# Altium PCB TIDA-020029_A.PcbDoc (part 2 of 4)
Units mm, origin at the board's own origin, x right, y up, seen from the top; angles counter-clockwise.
Board outline 267.5 x 53.5 mm, 2 copper layers (Top Layer, Bottom Layer), stack 1.575 mm thick; 255 components, 134 nets, 990 pads, 1977 vias.
Unrouted connection lines stored in the file: 9.
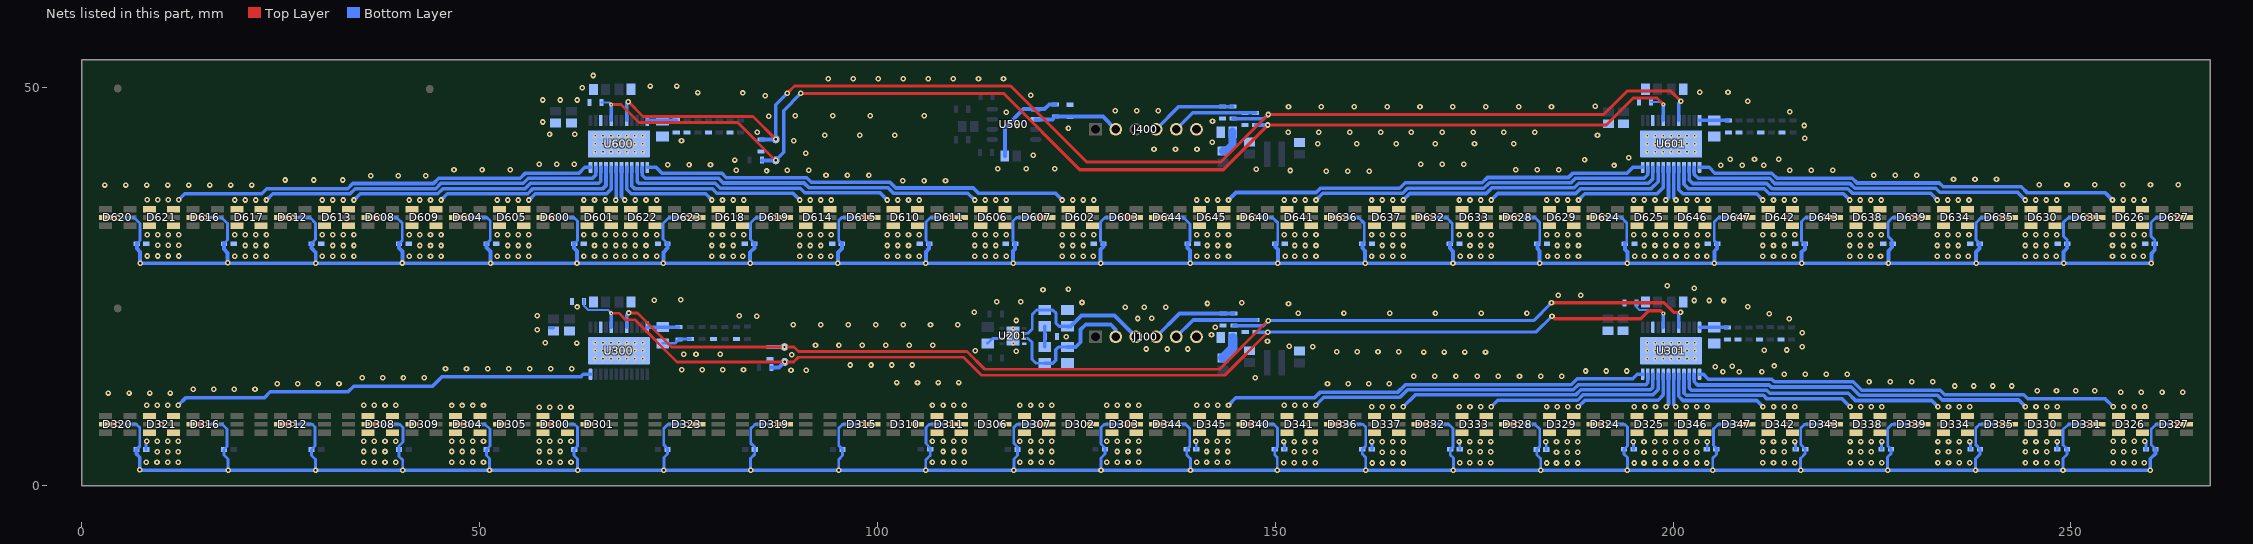
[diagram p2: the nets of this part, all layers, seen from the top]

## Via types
v1: diameter 0.7, hole 0.3, Top Layer to Bottom Layer, tented both sides, 1881 vias
v2: diameter 0.5, hole 0.2, Top Layer to Bottom Layer, tented both sides, 96 vias

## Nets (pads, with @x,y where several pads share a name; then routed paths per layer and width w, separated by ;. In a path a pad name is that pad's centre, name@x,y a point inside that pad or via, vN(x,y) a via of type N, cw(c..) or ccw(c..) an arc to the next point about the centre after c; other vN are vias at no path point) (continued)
1OUT11: C302.2 D321.1 D321.3 D321.4 D321.6 U300.24 | length 54.5
  Bottom Layer w0.254: v1@8.059,5.507 v1(8.128,5.577)
  Bottom Layer w0.35: C302.2@8.059,4.535 v1@8.059,5.507
  Bottom Layer w0.45: v1(12.123,10.098) 13.088,11.063 22.962,11.063 23.688,11.789 33.452,11.789 34.163,12.501 44.059,12.501 45.212,13.654 62.662,13.654 63.008,14 U300.24@63.925,14
  other v1: 8.103,2.908 9.432,2.908 10.761,2.908 12.09,2.908 9.464,4.256 10.794,4.256 12.123,4.256 9.457,5.577 10.787,5.577 12.116,5.577 10,7.7 8.135,10.098 9.464,10.098 10.794,10.098
2OUT0: C332.2 D326.1 D326.3 D326.4 D326.6 U301.13 | length 54.7
  Bottom Layer w0.35: v1(259.309,5.559) 259.445,5.423 C332.2@259.445,4.561
  Bottom Layer w0.45: U301.13@203.325,14 203.827,14 204.445,13.383 212.423,13.383 212.763,13.042 222.661,13.042 ; 222.733,12.976 223.719,11.99 233.576,11.99 234.163,11.404 244.092,11.404 244.577,10.919 254.3,10.919 v1(255.321,9.898)
  other v1: 255.321,2.891 256.65,2.891 257.979,2.891 259.209,2.891 255.321,4.264 256.65,4.264 257.979,4.264 255.321,5.559 256.65,5.559 257.979,5.559 256.65,9.898 257.979,9.898 259.309,9.898
2OUT1: C331.2 D330.1 D330.3 D330.4 D330.6 U301.14 | length 44.9
  Bottom Layer w0.254: C331.2@248.285,4.588 C331.2@248.312,4.561
  Bottom Layer w0.35: C331.2@248.285,4.588 v1(248.285,5.534)
  Bottom Layer w0.45: U301.14@202.675,14 202.675,13.05 203.085,12.64 212.109,12.64 212.357,12.392 222.392,12.392 223.444,11.34 233.233,11.34 233.82,10.754 243.441,10.754 v1(244.297,9.898)
  other v1: 244.297,2.865 245.626,2.865 246.956,2.865 248.285,2.865 244.297,4.239 245.626,4.239 246.956,4.239 244.297,5.534 245.626,5.534 246.956,5.534 245.626,9.898 246.956,9.898 248.285,9.898
2OUT2: C330.2 D334.1 D334.3 D334.4 D334.6 U301.15 | length 35
  Bottom Layer w0.35: v1(237.287,5.534) 237.388,5.432 C330.2@237.388,4.561
  Bottom Layer w0.45: U301.15@202.025,14 202.025,12.276 202.311,11.99 211.753,11.99 212.139,11.605 222.021,11.605 222.936,10.69 232.507,10.69 v1(233.299,9.898)
  other v1: 233.299,2.865 234.628,2.865 235.958,2.865 237.287,2.865 233.299,4.239 234.628,4.239 235.958,4.239 233.299,5.534 234.628,5.534 235.958,5.534 234.628,9.898 235.958,9.898 237.287,9.898
2OUT3: C329.2 D338.1 D338.3 D338.4 D338.6 U301.16 | length 25
  Bottom Layer w0.254: v1@226.204,5.5 v1(226.238,5.534)
  Bottom Layer w0.35: C329.2@226.204,4.561 v1@226.204,5.5
  Bottom Layer w0.45: U301.16@201.375,14 201.375,11.616 201.651,11.34 211.364,11.34 211.811,10.893 221.255,10.893 v1(222.25,9.898)
  other v1: 222.25,2.865 223.579,2.865 224.909,2.865 226.238,2.865 222.25,4.239 223.579,4.239 224.909,4.239 222.25,5.534 223.579,5.534 224.909,5.534 223.579,9.898 224.909,9.898 226.238,9.898
2OUT4: C328.2 D342.1 D342.3 D342.4 D342.6 U301.17 | length 14.9
  Bottom Layer w0.35: v1(215.288,5.534) 215.406,5.416 C328.2@215.406,4.561
  Bottom Layer w0.45: U301.17@200.725,14 200.725,11.209 201.244,10.69 210.51,10.69 v1(211.303,9.898)
  other v1: 211.3,2.865 212.629,2.865 213.958,2.865 215.288,2.865 211.3,4.239 212.629,4.239 213.958,4.239 211.3,5.534 212.629,5.534 213.958,5.534 212.632,9.898 213.961,9.898 215.29,9.898
2OUT5: C327.2 D346.1 D346.3 D346.4 D346.6 U301.18 | length 5.2
  Bottom Layer w0.254: C327.2@204.25,4.561 C327.2@204.313,4.624
  Bottom Layer w0.35: C327.2@204.313,4.624 v1(204.313,5.509)
  Bottom Layer w0.45: U301.18@200.075,14 200.075,10.153 v1@200.325,9.903
  other v1: 200.325,2.84 201.654,2.84 202.984,2.84 204.213,2.84 200.325,4.213 201.654,4.213 202.984,4.213 200.325,5.509 201.654,5.509 202.984,5.509 200.325,9.898 201.654,9.898 202.984,9.898 204.313,9.898
2OUT6: C326.2 D325.1 D325.3 D325.4 D325.6 U301.19 | length 5.2
  Bottom Layer w0.254: v1(195.021,5.509) v1@195.039,5.491
  Bottom Layer w0.35: C326.2@195.039,4.561 v1@195.039,5.491
  Bottom Layer w0.45: v1@199.111,9.903 199.425,10.217 U301.19@199.425,14
  other v1: 195.121,2.842 196.35,2.842 197.68,2.842 199.009,2.842 196.35,4.213 197.68,4.213 199.009,4.213 196.35,5.509 197.68,5.509 199.009,5.509 195.139,9.898 196.468,9.898 197.797,9.898 199.126,9.898
2OUT7: C325.2 D329.1 D329.3 D329.4 D329.6 U301.20 | length 14.9
  Bottom Layer w0.254: v1(184.023,5.509) v1@184.059,5.473
  Bottom Layer w0.35: C325.2@184.059,4.535 v1@184.059,5.473
  Bottom Layer w0.45: v1@188.087,9.903 188.925,10.741 198.12,10.741 198.775,11.396 U301.20@198.775,14
  other v1: 184.123,2.842 185.352,2.842 186.682,2.842 188.011,2.842 185.352,4.213 186.682,4.213 188.011,4.213 185.352,5.509 186.682,5.509 188.011,5.509 184.099,9.898 185.428,9.898 186.758,9.898 188.087,9.898
2OUT8: C324.2 D333.1 D333.3 D333.4 D333.6 U301.21 | length 24.8
  Bottom Layer w0.35: v1(173.101,5.534) 173.193,5.442 C324.2@173.193,4.561
  Bottom Layer w0.45: v1(177.14,9.898) 177.983,10.741 188.006,10.741 188.656,11.391 197.429,11.391 198.125,12.087 U301.21@198.125,14
  other v1: 173.201,2.867 174.43,2.867 175.76,2.867 177.089,2.867 174.43,4.239 175.76,4.239 177.089,4.239 174.43,5.534 175.76,5.534 177.089,5.534 173.152,9.898 174.481,9.898 175.81,9.898
2OUT9: C321.2 D337.1 D337.3 D337.4 D337.6 U301.22 | length 35
  Bottom Layer w0.35: v1(162.103,5.509) 162.144,5.467 C321.2@162.144,4.561
  Bottom Layer w0.45: v1(166.091,9.898) 167.584,11.391 187.737,11.391 188.387,12.041 197.159,12.041 197.475,12.357 U301.22@197.475,14
  other v1: 162.203,2.842 163.432,2.842 164.761,2.842 166.091,2.842 163.432,4.213 164.761,4.213 166.091,4.213 163.432,5.509 164.761,5.509 166.091,5.509 162.103,9.898 163.432,9.898 164.761,9.898
2OUT10: C320.2 D341.1 D341.3 D341.4 D341.6 U301.23 | length 45
  Bottom Layer w0.35: v1(151.054,5.534) 151.146,5.442 C320.2@151.146,4.569
  Bottom Layer w0.45: v1(155.092,10.098) 156.078,11.084 165.671,11.084 166.629,12.041 187.467,12.041 188.117,12.691 196.59,12.691 196.825,12.926 U301.23@196.825,14
  other v1: 151.054,2.867 152.383,2.867 153.712,2.867 155.042,2.867 152.383,4.239 153.712,4.239 155.042,4.239 152.383,5.534 153.712,5.534 155.042,5.534 151.105,10.098 152.434,10.098 153.763,10.098
2OUT11: C319.2 D345.1 D345.3 D345.4 D345.6 U301.24 | length 54.7
  Bottom Layer w0.254: v1(140.03,5.577) v1@140.071,5.536
  Bottom Layer w0.35: C319.2@140.071,4.561 v1@140.071,5.536
  Bottom Layer w0.45: v1(144.12,10.098) 145.042,11.02 154.94,11.02 155.676,11.756 165.424,11.756 166.359,12.691 187.198,12.691 187.941,13.433 194.945,13.433 195.512,14 U301.24@196.175,14
  other v1: 140.13,2.91 141.359,2.91 142.689,2.91 144.018,2.91 141.359,4.281 142.689,4.281 144.018,4.281 141.359,5.577 142.689,5.577 144.018,5.577 140.132,10.098 141.461,10.098 142.79,10.098
3OUT0: C615.2 D602.1 D602.3 D602.4 D602.6 U600.13 | length 53.8
  Bottom Layer w0.45: U600.13@71.075,40 72.157,40 72.873,39.284 80.401,39.284 81.001,38.685 91.095,38.685 91.669,38.111 101.575,38.111 102.276,37.41 112.024,37.41 112.7,36.735 122.37,36.735 v1(123.208,35.897)
  other v1: 123.208,28.834 124.538,28.834 125.867,28.834 127.096,28.834 123.208,30.182 124.538,30.182 125.867,30.182 123.208,31.528 124.538,31.528 125.867,31.528 127.196,31.528 124.538,35.897 125.867,35.897 127.196,35.897
3OUT1: C614.2 D606.1 D606.3 D606.4 D606.6 U600.14 | length 44.1
  Bottom Layer w0.45: U600.14@70.425,40 70.425,39.005 70.796,38.634 80.02,38.634 80.62,38.035 90.765,38.035 91.338,37.461 101.306,37.461 102.006,36.76 111.347,36.76 v1(112.21,35.897)
  other v1: 112.21,28.834 113.539,28.834 114.869,28.834 116.198,28.834 112.21,30.182 113.539,30.182 114.869,30.182 112.21,31.528 113.539,31.528 114.869,31.528 116.198,31.528 113.539,35.897 114.869,35.897 116.198,35.897
3OUT2: C613.2 D610.1 D610.3 D610.4 D610.6 U600.15 | length 34.2
  Bottom Layer w0.45: U600.15@69.775,40 69.775,38.232 70.023,37.984 79.614,37.984 80.213,37.385 90.282,37.385 90.856,36.811 100.323,36.811 v1(101.237,35.897)
  other v1: 101.237,28.834 102.567,28.834 103.896,28.834 105.225,28.834 101.237,30.182 102.567,30.182 103.896,30.182 101.237,31.528 102.567,31.528 103.896,31.528 105.225,31.528 102.567,35.897 103.896,35.897 105.225,35.897
3OUT3: C612.2 D614.1 D614.3 D614.4 D614.6 U600.16 | length 24.2
  Bottom Layer w0.45: U600.16@69.125,40 69.125,37.653 69.444,37.334 79.208,37.334 79.807,36.735 89.376,36.735 v1(90.214,35.897)
  other v1: 90.214,28.834 91.543,28.834 92.872,28.834 94.102,28.834 90.214,30.182 91.543,30.182 92.872,30.182 90.214,31.528 91.543,31.528 92.872,31.528 94.202,31.528 91.543,35.897 92.872,35.897 94.202,35.897
3OUT4: C611.2 D618.1 D618.3 D618.4 D618.6 U600.17 | length 14
  Bottom Layer w0.45: U600.17@68.475,40 68.475,37.26 69.051,36.684 78.403,36.684 v1(79.19,35.897)
  other v1: 79.19,28.834 80.519,28.834 81.849,28.834 83.078,28.834 79.19,30.182 80.519,30.182 81.849,30.182 79.19,31.528 80.519,31.528 81.849,31.528 83.178,31.528 80.519,35.897 81.849,35.897 83.178,35.897
3OUT5: C610.2 D622.1 D622.3 D622.4 D622.6 U600.18 | length 4.3
  Bottom Layer w0.45: U600.18@67.825,40 67.825,36.315 v1(68.243,35.897)
  other v1: 68.243,28.834 69.572,28.834 70.901,28.834 72.231,28.834 68.243,30.182 69.572,30.182 70.901,30.182 68.243,31.528 69.572,31.528 70.901,31.528 72.231,31.528 69.572,35.897 70.901,35.897 72.231,35.897
3OUT6: C609.2 D601.1 D601.3 D601.4 D601.6 U600.19 | length 4.1
  Bottom Layer w0.45: v1(67.088,35.897) 67.175,35.984 U600.19@67.175,40
  other v1: 63.1,28.834 64.429,28.834 65.759,28.834 67.088,28.834 64.429,30.182 65.759,30.182 67.088,30.182 63.1,31.528 64.429,31.528 65.759,31.528 67.088,31.528 63.1,35.897 64.429,35.897 65.759,35.897
3OUT7: C608.2 D605.1 D605.3 D605.4 D605.6 U600.20 | length 13.6
  Bottom Layer w0.45: v1(56.185,35.897) 56.972,36.684 65.938,36.684 66.525,37.271 U600.20@66.525,40
  other v1: 52.197,28.834 53.526,28.834 54.856,28.834 56.185,28.834 53.526,30.182 54.856,30.182 56.185,30.182 52.197,31.528 53.526,31.528 54.856,31.528 56.185,31.528 52.197,35.897 53.526,35.897 54.856,35.897
3OUT8: C607.2 D609.1 D609.3 D609.4 D609.6 U600.21 | length 23.8
  Bottom Layer w0.45: v1(45.138,35.897) 45.925,36.684 56.053,36.684 56.703,37.334 65.498,37.334 65.875,37.711 U600.21@65.875,40
  other v1: 41.15,28.834 42.479,28.834 43.809,28.834 45.138,28.834 42.479,30.182 43.809,30.182 45.138,30.182 41.15,31.528 42.479,31.528 43.809,31.528 45.138,31.528 41.15,35.897 42.479,35.897 43.809,35.897
3OUT9: C604.2 D613.1 D613.3 D613.4 D613.6 U600.22 | length 33.8
  Bottom Layer w0.45: v1(34.188,35.897) 34.963,36.672 44.742,36.672 45.405,37.334 55.728,37.334 56.378,37.984 64.957,37.984 65.225,38.252 U600.22@65.225,40
  other v1: 30.201,28.834 31.53,28.834 32.859,28.834 34.188,28.834 31.53,30.182 32.859,30.182 34.188,30.182 30.201,31.528 31.53,31.528 32.859,31.528 34.188,31.528 30.201,35.897 31.53,35.897 32.859,35.897
3OUT10: C603.2 D617.1 D617.3 D617.4 D617.6 U600.23 | length 43.7
  Bottom Layer w0.45: v1(23.19,35.897) 23.965,36.672 33.693,36.672 34.343,37.322 44.473,37.322 45.136,37.984 55.458,37.984 56.108,38.634 64.18,38.634 64.575,39.029 U600.23@64.575,40
  other v1: 19.202,28.834 20.532,28.834 21.861,28.834 23.19,28.834 20.532,30.182 21.861,30.182 23.19,30.182 19.202,31.528 20.532,31.528 21.861,31.528 23.19,31.528 19.202,35.897 20.532,35.897 21.861,35.897
3OUT11: C602.2 D621.1 D621.3 D621.4 D621.6 U600.24 | length 53.4
  Bottom Layer w0.45: v1(12.174,35.922) 12.936,36.684 22.606,36.684 23.244,37.322 33.401,37.322 34.051,37.972 44.196,37.972 44.858,38.634 55.093,38.634 55.743,39.284 62.493,39.284 63.209,40 U600.24@63.925,40
  other v1: 8.186,28.859 9.515,28.859 10.844,28.859 12.174,28.859 9.515,30.207 10.844,30.207 12.174,30.207 8.186,31.553 9.515,31.553 10.844,31.553 12.174,31.553 8.186,35.922 9.515,35.922 10.844,35.922
4OUT0: C632.2 D626.1 D626.3 D626.4 D626.6 U601.13 | length 53.6
  Bottom Layer w0.45: U601.13@203.325,40 204.532,40 204.532,39.998 205.257,39.273 212.42,39.273 213.07,38.623 222.526,38.623 223.114,38.035 233.46,38.035 233.947,37.548 243.789,37.548 244.551,36.786 254.349,36.786 v1(255.238,35.897)
  other v1: 255.238,28.834 256.567,28.834 257.896,28.834 259.125,28.834 255.238,30.182 256.567,30.182 257.896,30.182 255.238,31.528 256.567,31.528 257.896,31.528 259.225,31.528 256.567,35.897 257.896,35.897 259.225,35.897
4OUT1: C631.2 D630.1 D630.3 D630.4 D630.6 U601.14 | length 43.8
  Bottom Layer w0.45: U601.14@202.675,40 202.675,39.097 203.15,38.623 212.151,38.623 212.801,37.973 222.236,37.973 222.824,37.385 233.005,37.385 233.529,36.86 243.301,36.86 v1(244.265,35.897)
  other v1: 244.265,28.834 245.594,28.834 246.923,28.834 248.153,28.834 244.265,30.182 245.594,30.182 246.923,30.182 244.265,31.528 245.594,31.528 246.923,31.528 248.253,31.528 245.594,35.897 246.923,35.897 248.253,35.897
4OUT2: C630.2 D634.1 D634.3 D634.4 D634.6 U601.15 | length 33.8
  Bottom Layer w0.45: U601.15@202.025,40 202.025,38.415 202.467,37.973 211.796,37.973 212.446,37.323 221.967,37.323 222.555,36.735 232.378,36.735 v1(233.216,35.897)
  other v1: 233.216,28.834 234.545,28.834 235.874,28.834 237.104,28.834 233.216,30.182 234.545,30.182 235.874,30.182 233.216,31.528 234.545,31.528 235.874,31.528 237.204,31.528 234.545,35.897 235.874,35.897 237.204,35.897
4OUT3: C629.2 D638.1 D638.3 D638.4 D638.6 U601.16 | length 23.8
  Bottom Layer w0.45: U601.16@201.375,40 201.375,37.892 201.945,37.323 211.452,37.323 212.102,36.673 221.416,36.673 v1(222.192,35.897)
  other v1: 222.192,28.834 223.521,28.834 224.851,28.834 226.08,28.834 222.192,30.182 223.521,30.182 224.851,30.182 222.192,31.528 223.521,31.528 224.851,31.528 226.18,31.528 223.521,35.897 224.851,35.897 226.18,35.897
4OUT4: C628.2 D642.1 D642.3 D642.4 D642.6 U601.17 | length 13.9
  Bottom Layer w0.45: U601.17@200.725,40 200.725,37.203 201.256,36.673 210.52,36.673 v1(211.296,35.897)
  other v1: 211.296,28.834 212.625,28.834 213.954,28.834 215.183,28.834 211.296,30.182 212.625,30.182 213.954,30.182 211.296,31.528 212.625,31.528 213.954,31.528 215.283,31.528 212.625,35.897 213.954,35.897 215.283,35.897
4OUT5: C627.2 D646.1 D646.3 D646.4 D646.6 U601.18 | length 4.3
  Bottom Layer w0.45: U601.18@200.075,40 200.075,36.101 200.279,35.897 v1(200.374,35.897)
  other v1: 200.374,28.834 201.703,28.834 203.032,28.834 204.261,28.834 200.374,30.182 201.703,30.182 203.032,30.182 200.374,31.528 201.703,31.528 203.032,31.528 204.361,31.528 201.703,35.897 203.032,35.897 204.361,35.897
4OUT6: C626.2 D625.1 D625.3 D625.4 D625.6 U601.19 | length 4.3
  Bottom Layer w0.45: v1(199.06,35.897) 199.136,35.897 199.425,36.186 U601.19@199.425,40
  other v1: 195.172,28.834 196.401,28.834 197.731,28.834 199.06,28.834 196.401,30.182 197.731,30.182 199.06,30.182 195.072,31.528 196.401,31.528 197.731,31.528 199.06,31.528 195.072,35.897 196.401,35.897 197.731,35.897
4OUT7: C625.2 D629.1 D629.3 D629.4 D629.6 U601.20 | length 13.8
  Bottom Layer w0.45: v1(188.112,35.897) 188.9,36.684 197.993,36.684 198.775,37.466 U601.20@198.775,40
  other v1: 184.225,28.834 185.454,28.834 186.783,28.834 188.112,28.834 185.454,30.182 186.783,30.182 188.112,30.182 184.125,31.528 185.454,31.528 186.783,31.528 188.112,31.528 184.125,35.897 185.454,35.897 186.783,35.897
4OUT8: C624.2 D633.1 D633.3 D633.4 D633.6 U601.21 | length 23.7
  Bottom Layer w0.45: v1(177.138,35.897) 177.951,36.71 187.782,36.71 188.407,37.334 197.271,37.334 198.125,38.188 U601.21@198.125,40
  other v1: 173.25,28.834 174.479,28.834 175.809,28.834 177.138,28.834 174.479,30.182 175.809,30.182 177.138,30.182 173.15,31.528 174.479,31.528 175.809,31.528 177.138,31.528 173.15,35.897 174.479,35.897 175.809,35.897
4OUT9: C621.2 D637.1 D637.3 D637.4 D637.6 U601.22 | length 33.9
  Bottom Layer w0.45: v1(166.088,35.897) 166.901,36.71 176.53,36.71 177.241,37.421 187.574,37.421 188.138,37.984 196.904,37.984 197.475,38.555 U601.22@197.475,40
  other v1: 162.1,28.834 163.429,28.834 164.759,28.834 166.088,28.834 163.429,30.182 164.759,30.182 166.088,30.182 162.1,31.528 163.429,31.528 164.759,31.528 166.088,31.528 162.1,35.897 163.429,35.897 164.759,35.897
4OUT10: C620.2 D641.1 D641.3 D641.4 D641.6 U601.23 | length 44
  Bottom Layer w0.45: v1(155.118,35.897) 155.956,36.735 166.007,36.735 166.631,37.36 176.225,37.36 176.936,38.071 187.173,38.071 187.736,38.634 196.387,38.634 196.825,39.072 U601.23@196.825,40
  other v1: 151.23,28.834 152.459,28.834 153.789,28.834 155.118,28.834 152.459,30.182 153.789,30.182 155.118,30.182 151.13,31.528 152.459,31.528 153.789,31.528 155.118,31.528 151.13,35.897 152.459,35.897 153.789,35.897
4OUT11: C619.2 D645.1 D645.3 D645.4 D645.6 U601.24 | length 53.8
  Bottom Layer w0.45: v1(144.12,35.897) 145.059,36.837 155.138,36.837 155.687,37.385 165.633,37.385 166.33,38.081 176.028,38.081 176.667,38.721 186.868,38.721 187.431,39.284 194.241,39.284 194.957,40 U601.24@196.175,40
  other v1: 140.132,28.834 141.461,28.834 142.79,28.834 144.12,28.834 141.461,30.182 142.79,30.182 144.12,30.182 140.132,31.528 141.461,31.528 142.79,31.528 144.12,31.528 140.132,35.897 141.461,35.897 142.79,35.897
CANH: C203.1 J100.2 R204.2 U201.7 | length 19
  Bottom Layer w0.35: U201.7@118.443,18.494 118.927,18.494 119.405,18.016 119.405,15.883 119.913,15.375 R204.2@121.031,15.375
  Bottom Layer w0.4: R204.2@121.031,15.375 122.022,15.375 122.403,15.756 122.403,17.076 122.733,17.407 C203.1@123.876,17.407
  Bottom Layer w0.5: C203.1@123.876,17.407 124.917,17.407 125.527,18.016 125.527,19.591 126.213,20.277 129.272,20.277 129.94,19.609 J100.2@129.94,18.7
CANL: C206.1 J100.3 R207.1 U201.6 | length 19.6
  Bottom Layer w0.35: U201.6@118.443,19.144 118.933,19.144 119.456,19.667 119.456,21.521 119.99,22.055 R207.1@121.031,22.055
  Bottom Layer w0.4: R207.1@121.031,22.055 122.048,22.055 122.453,21.65 122.453,20.378 122.809,20.023 C206.1@123.876,20.023
  Bottom Layer w0.5: C206.1@123.876,20.023 124.257,20.023 125.628,21.394 129.786,21.394 J100.3@132.48,18.7
ERR: C334.1 C335.1 C634.1 C635.1 R101.2 R308.1 R401.2 R608.1 TP301.1 TP601.1 U300.5 U301.5 U600.5 U601.5 | length 315.9
  Top Layer w0.35: v2(66.525,21.675) 67.501,21.675 68.326,20.85 69.494,20.85 74.803,15.542 v1@88.316,15.542 ; v2(66.525,47.891) 67.767,47.891 70.033,45.625 82.431,45.625 87.18,40.875 v1(87.208,40.875) ; v1(88.332,15.542) 89.459,15.542 90.043,16.126 110.795,16.126 113.055,13.865 143.652,13.865 v1(149.073,19.286)
  Top Layer w0.4: v1(90.373,49.298) 115.834,49.298 125.425,39.707 143.485,39.707 149.075,45.297 v1(149.075,45.328) 191.609,45.328 195.005,48.724 197.979,48.724 v2(198.775,47.928) ; v1(184.785,21.307) 185.117,20.975 195.93,20.975 196.926,21.971 198.436,21.971 v2(198.775,21.632)
  Bottom Layer w0.254: C335.1@63.121,23.363 C335.1@63.121,23.165 63.121,22.569 63.62,22.069 64.991,22.069 64.994,22.073 65.117,22.073 65.12,22.069 66.131,22.069 v2(66.525,21.675) ; C635.1@65.318,48.165 66.251,48.165 v2(66.525,47.891) ; R608.1@85.455,40.901 R608.1@85.48,40.875 ; C334.1@195.431,23.266 C334.1@195.431,22.966 195.431,22.391 195.753,22.069 198.338,22.069 v2(198.775,21.632) ; C634.1@197.23,48.241 198.462,48.241 v2(198.775,47.928)
  Bottom Layer w0.4: U600.5@66.525,45.9 v2(66.525,47.891) ; v1(87.208,40.875) 88.214,41.882 88.214,47.139 v1(90.373,49.298) ; v1(149.073,19.286) 182.764,19.286 v1(184.785,21.307) ; U301.5@198.775,19.9 v2(198.775,21.632)
  Bottom Layer w0.45: U300.5@66.525,19.9 v2(66.525,21.675) ; R401.2@147.523,45.328 v1(149.075,45.328) ; R101.2@147.588,19.286 v1(149.073,19.286) ; U601.5@198.775,45.9 v2(198.775,47.928)
  Bottom Layer w0.5: R608.1@85.48,40.875 v1(87.208,40.875) ; R308.1@86.656,14.842 87.632,14.842 v1(88.332,15.542)
FS: R100.2 R309.2 R400.2 R609.2 TP300.1 TP600.1 U300.8 U301.8 U600.8 U601.8 | length 308.6
  Top Layer w0.35: v1(68.682,48.249) 70.543,46.387 84.353,46.387 87.208,43.533 v1(87.208,43.517) ; v1(68.725,21.7) 69.838,21.7 74.117,17.421 v1(88.309,17.421) 89.513,17.421 90.072,16.862 111.252,16.862 113.487,14.627 142.993,14.627 v1(149.1,20.734)
  Top Layer w0.4: v1(88.646,49.298) 89.57,50.222 116.731,50.222 126.282,40.672 143.129,40.672 143.129,40.678 v1(149.1,46.649) 191.278,46.649 194.217,49.587 199.732,49.587 v1(200.994,48.325) ; v1(184.725,22.971) 198.869,22.971 200.065,21.775 v1(200.943,21.775)
  Bottom Layer w0.4: U600.8@68.475,45.9 68.475,48.042 v1(68.682,48.249) ; v1(87.208,43.517) 87.208,47.86 v1(88.646,49.298) ; v1(149.1,20.734) 182.475,20.734 v1@184.725,22.984 ; U301.8@200.725,19.9 200.725,21.557 v1(200.943,21.775)
  Bottom Layer w0.45: U300.8@68.475,19.9 68.475,21.45 v1(68.725,21.7) ; R400.2@144.678,46.115 148.567,46.115 v1(149.1,46.649) ; R100.2@144.805,20.109 148.475,20.109 v1(149.1,20.734) ; U601.8@200.725,45.9 200.725,48.056 v1(200.994,48.325)
  Bottom Layer w0.5: R609.2@85.379,43.517 v1(87.208,43.517) ; R309.2@86.479,17.421 v1(88.309,17.421)
GND: C101.2 C102.2 C103.2 C108.2 C109.2 C203.2 C204.2 C205.2 C206.2 C300.2 C301.2 C302.1 C303.1 C304.1 C305.2 C306.2 C307.1 C308.1 C309.1 C310.1 C311.1 C312.1 C313.1 C314.1 C315.1 C316.1 C317.2 C318.2 C319.1 C320.1 C321.1 C322.2 C323.2 C324.1 C325.1 C326.1 C327.1 C328.1 C329.1 C330.1 C331.1 C332.1 C333.1 C334.2 C335.2 C401.2 C402.2 C403.2 C404.2 C405.2 C500.2 C501.2 C502.2 C600.2 C601.2 C602.1 C603.1 C604.1 C605.2 C606.2 C607.1 C608.1 C609.1 C610.1 C611.1 C612.1 C613.1 C614.1 C615.1 C616.1 C617.2 C618.2 C619.1 C620.1 C621.1 C622.2 C623.2 C624.1 C625.1 C626.1 C627.1 C628.1 C629.1 C630.1 C631.1 C632.1 C633.1 C634.2 C635.2 D300.2 D303.2 D304.2 D307.2 D308.2 D311.2 D312.2 D315.2 D316.2 D319.2 D320.2 D323.2 D324.2 D327.2 D328.2 D331.2 D332.2 D335.2 D336.2 D339.2 D340.2 D343.2 D344.2 D347.2 D600.2 D603.2 D604.2 D607.2 D608.2 D611.2 D612.2 D615.2 D616.2 D619.2 D620.2 D623.2 D624.2 D627.2 D628.2 D631.2 D632.2 D635.2 D636.2 D639.2 D640.2 D643.2 D644.2 D647.2 J100.6 J400.6 R303.1 R304.1 R305.1 R306.1 R309.1 R313.1 R314.1 R315.1 R316.1 R603.1 R604.1 R605.1 R606.1 R609.1 R613.1 R614.1 R615.1 R616.1 U201.2 U201.8 U201.9@117.043,18.819 U300.3 U300.25 U301.3 U301.25 U500.5 U600.3 U600.25 U601.3 U601.25 | length 1011.1
  Top Layer w0.6: D320.2@2.975,7.7 v1(4.5,7.7) ; D620.2@2.975,33.7 v1(4.5,33.7) ; D316.2@13.975,7.7 v1(15.5,7.7) ; D616.2@13.975,33.7 v1(15.5,33.7) ; D312.2@24.975,7.7 v1(26.5,7.7) ; D612.2@24.975,33.7 v1(26.5,33.7) ; D308.2@35.975,7.7 v1(37.5,7.7) ; D608.2@35.975,33.7 v1(37.5,33.7) ; D304.2@46.975,7.7 v1(48.5,7.7) ; D604.2@46.975,33.7 v1(48.5,33.7) ; D300.2@57.975,7.7 v1(59.5,7.7) ; D600.2@57.975,33.7 v1(59.5,33.7) ; v1(76,7.7) D323.2@77.525,7.7 ; v1(76,33.7) D623.2@77.525,33.7 ; v1(87,7.7) D319.2@88.525,7.7 ; v1(87,33.7) D619.2@88.525,33.7 ; v1(98,7.7) D315.2@99.525,7.7 ; v1(98,33.7) D615.2@99.525,33.7 ; v1(109,7.7) D311.2@110.525,7.7 ; v1(109,33.7) D611.2@110.525,33.7 ; v1(120,7.7) D307.2@121.525,7.7 ; v1(120,33.7) D607.2@121.525,33.7 ; v1(131,7.7) D303.2@132.525,7.7 ; v1(131,33.7) D603.2@132.525,33.7 ; D344.2@134.975,7.7 v1(136.5,7.7) ; D644.2@134.975,33.7 v1(136.5,33.7) ; D340.2@145.975,7.7 v1(147.5,7.7) ; D640.2@145.975,33.7 v1(147.5,33.7) ; D336.2@156.975,7.7 v1(158.5,7.7) ; D636.2@156.975,33.7 v1(158.5,33.7) ; D332.2@167.975,7.7 v1(169.5,7.7) ; D632.2@167.975,33.7 v1(169.5,33.7) ; D328.2@178.975,7.7 v1(180.5,7.7) ; D628.2@178.975,33.7 v1(180.5,33.7) ; D324.2@189.975,7.7 v1(191.5,7.7) ; D624.2@189.975,33.7 v1(191.5,33.7) ; v1(208,7.7) D347.2@209.525,7.7 ; v1(208,33.7) D647.2@209.525,33.7 ; v1(219,7.7) D343.2@220.525,7.7 ; v1(219,33.7) D643.2@220.525,33.7 ; v1(230,7.7) D339.2@231.525,7.7 ; v1(230,33.7) D639.2@231.525,33.7 ; v1(241,7.7) D335.2@242.525,7.7 ; v1(241,33.7) D635.2@242.525,33.7 ; v1(252,7.7) D331.2@253.525,7.7 ; v1(252,33.7) D631.2@253.525,33.7 ; v1(263,7.7) D327.2@264.525,7.7 ; v1(263,33.7) D627.2@264.525,33.7
  Bottom Layer w0.254: C316.1@75.058,18.388 C316.1@75.108,18.438
  Bottom Layer w0.35: v1(4.5,7.7) 6.876,7.7 7.264,7.312 7.264,4.94 C302.1@6.859,4.535 ; v1(4.5,33.7) 6.557,33.7 7.313,32.944 7.313,30.813 C602.1@6.9,30.4 ; v1(15.5,7.7) 17.656,7.7 18.237,7.119 18.237,4.913 C303.1@17.859,4.535 17.859,3.85 18.364,3.345 v1(18.364,1.922) ; v1(15.5,33.7) 17.55,33.7 18.288,32.962 18.288,30.86 C603.1@17.859,30.43 ; v1(26.5,7.7) 28.963,7.7 29.286,7.377 29.286,4.962 C304.1@28.859,4.535 28.859,3.802 29.362,3.298 v1(29.362,1.922) ; v1(26.5,33.7) 28.641,33.7 29.362,32.979 29.362,30.934 28.859,30.43 C604.1@28.859,30.4 ; v1(37.5,7.7) 39.947,7.7 40.361,7.287 40.361,5.491 39.859,4.989 C307.1@39.859,4.535 39.859,3.665 40.335,3.189 v1(40.335,1.922) ; v1(37.5,33.7) 39.55,33.7 40.257,32.993 40.257,30.798 C607.1@39.859,30.4 ; v1(48.5,7.7) 50.685,7.7 51.283,7.103 51.283,4.959 C308.1@50.859,4.535 50.859,3.769 51.232,3.396 v1(51.232,1.922) ; v1(48.5,33.7) 50.885,33.7 51.333,33.252 51.333,30.905 C608.1@50.859,30.43 ; C306.2@58.765,19.818 C306.2@59.281,19.818 ; v1(59.5,7.7) 61.932,7.7 62.281,7.351 62.281,4.957 C309.1@61.859,4.535 61.859,3.774 62.306,3.326 v1(62.306,1.922) ; v1(59.5,33.7) 61.82,33.7 62.281,33.239 62.281,30.822 C609.1@61.859,30.4 ; R306.1@73,17.884 74.554,17.884 C316.1@75.058,18.388 ; v1(73.152,1.922) 73.152,3.527 73.604,3.979 C310.1@73.604,4.535 73.604,4.651 73.127,5.128 73.127,7.188 73.639,7.7 v1(76,7.7) ; C610.1@73.604,30.43 73.03,31.003 73.03,32.919 73.811,33.7 v1(76,33.7) ; C316.1@75.108,18.438 R305.1@76.5,18.438 ; v1(84.05,1.922) 84.05,3.422 84.572,3.945 C311.1@84.572,4.535 84.572,4.828 84.074,5.327 84.074,7.185 84.589,7.7 v1(87,7.7) ; C611.1@84.557,30.4 84.036,30.92 84.036,33.006 84.73,33.7 v1(87,33.7) ; v1(95.123,1.922) 95.123,3.294 95.604,3.775 C312.1@95.604,4.535 95.604,4.566 95.123,5.046 95.123,7.236 95.587,7.7 v1(98,7.7) ; C612.1@95.519,30.4 95.131,30.788 95.131,33.331 95.5,33.7 v1(98,33.7) ; v1(106.07,1.922) 106.07,3.218 106.62,3.767 C313.1@106.62,4.561 ; C613.1@106.5,30.4 106.102,30.798 106.102,33.132 106.67,33.7 v1(109,33.7) ; C313.1@106.604,4.535 106.604,4.747 106.079,5.272 106.079,7.279 106.5,7.7 v1(109,7.7) ; C204.2@113.843,17.879 114.458,18.494 U201.2@115.643,18.494 ; v1(117.145,1.922) 117.145,3.354 117.592,3.801 C314.1@117.592,4.535 117.592,4.864 117.119,5.337 117.119,7.319 117.5,7.7 v1(120,7.7) ; C614.1@117.3,30.4 117.034,30.666 117.034,33.234 117.5,33.7 v1(120,33.7) ; v1@128.067,1.922 v1(128.092,1.948) 128.092,3.46 128.604,3.971 C315.1@128.604,4.561 ; C615.1@128.4,30.4 128.016,30.784 128.016,33.128 128.588,33.7 v1(131,33.7) ; C315.1@128.6,4.716 128.102,5.215 128.102,7.302 128.5,7.7 v1(131,7.7) ; v1(136.5,7.7) 138.753,7.7 139.257,7.197 139.257,4.932 139.243,4.932 C319.1@138.871,4.561 138.871,3.848 139.344,3.375 v1(139.344,1.922) ; v1(136.5,33.7) 138.442,33.7 139.278,32.864 139.278,30.699 C619.1@138.979,30.4 ; v1(147.5,7.7) 149.828,7.7 150.28,7.247 150.28,4.889 150.266,4.889 C320.1@149.946,4.569 149.946,3.847 150.246,3.547 v1(150.246,1.922) ; v1(147.5,33.7) 149.643,33.7 150.313,33.031 150.313,30.7 C620.1@150.013,30.4 ; v1(158.5,7.7) 161.029,7.7 161.366,7.363 161.366,4.983 C321.1@160.944,4.561 160.944,3.975 161.366,3.553 v1(161.366,1.922) ; v1(158.5,33.7) 160.464,33.7 161.188,32.976 C621.1@161.188,30.614 ; v1(169.5,7.7) 171.799,7.7 172.327,7.171 172.327,4.831 172.263,4.831 C324.1@171.993,4.561 171.993,3.848 172.39,3.451 v1(172.39,1.922) ; v1(169.5,33.7) 171.513,33.7 172.237,32.976 172.237,30.687 C624.1@171.95,30.4 ; v1(180.5,7.7) 182.67,7.7 183.249,7.12 183.249,4.912 183.236,4.912 C325.1@182.859,4.535 182.859,3.929 183.363,3.425 v1(183.363,1.922) ; v1(180.5,33.7) 182.638,33.7 183.236,33.103 183.236,30.664 C625.1@182.956,30.385 ; v1(191.5,7.7) 193.922,7.7 194.259,7.363 194.259,4.981 C326.1@193.839,4.561 193.839,3.942 194.259,3.521 v1(194.259,1.922) ; v1(191.5,33.7) 193.509,33.7 194.183,33.027 194.183,30.633 C626.1@193.95,30.4 ; v1(204.991,1.922) 204.991,3.444 205.45,3.902 C327.1@205.45,4.561 ; C327.1@205.55,4.591 205.55,4.561 205.086,5.024 205.086,7.131 205.655,7.7 v1(208,7.7) ; C627.1@205.55,30.4 205.181,30.769 205.181,33.153 205.728,33.7 v1(208,33.7) ; v1(216.028,1.922) 216.028,3.427 216.606,4.004 C328.1@216.606,4.561 216.606,4.591 216.05,5.147 216.05,7.25 216.5,7.7 v1(219,7.7) ; C628.1@216.56,30.36 216.154,30.766 216.154,33.204 216.65,33.7 v1(219,33.7) ; v1(226.974,1.922) 226.974,3.573 227.404,4.003 C329.1@227.404,4.561 227,4.965 227,7.21 227.489,7.7 v1(230,7.7) ; C629.1@227.549,30.4 227.549,30.817 227.051,31.315 227.051,33.154 227.597,33.7 v1(230,33.7) ; v1(238.023,1.922) 238.023,3.375 238.588,3.94 C330.1@238.588,4.561 238.588,4.591 238.05,5.13 238.05,7.25 238.5,7.7 v1(241,7.7) ; C630.1@238.55,30.43 238.074,30.906 238.074,33.027 238.748,33.7 v1(241,33.7) ; v1(249.022,1.922) 249.022,3.404 249.512,3.895 C331.1@249.512,4.561 249.512,4.591 249.022,5.082 249.022,7.026 249.695,7.7 v1(252,7.7) ; C631.1@249.55,30.4 249.55,30.889 249.098,31.341 249.098,33.103 249.695,33.7 v1(252,33.7) ; C632.1@260.55,30.4 260.55,30.862 260.074,31.337 260.074,33.055 260.719,33.7 v1(263,33.7) ; C332.1@260.645,4.561 260.645,4.591 260.121,5.115 260.121,7.128 260.693,7.7 v1(263,7.7)
  Bottom Layer w0.45: C302.1@6.859,4.535 6.859,3.979 7.264,3.573 7.264,1.955 7.297,1.922 v1(18.364,1.922) v1(29.362,1.922) v1(40.335,1.922) v1(51.232,1.922) v1(62.306,1.922) v1(73.152,1.922) v1(84.05,1.922) v1(95.123,1.922) v1(106.07,1.922) v1(117.145,1.922) 128.067,1.922 v1(139.344,1.922) v1(150.246,1.922) v1(161.366,1.922) v1(172.39,1.922) v1(183.363,1.922) v1(194.259,1.922) v1(204.991,1.922) v1(216.028,1.922) v1(226.974,1.922) v1(238.023,1.922) v1(249.022,1.922) v1(259.963,1.922) 259.994,1.891 259.994,3.354 260.645,4.005 C332.1@260.645,4.561
  Bottom Layer w0.5: C602.1@6.9,30.4 6.9,29.798 7.316,29.382 v1(7.316,27.947) v1@18.263,27.947 ; C603.1@17.859,30.43 C603.1@17.859,30.4 17.859,29.724 18.319,29.263 v1(18.319,28.003) v1@18.263,27.947 ; C604.1@28.859,30.4 28.859,29.844 29.388,29.315 v1(29.388,27.947) ; C607.1@39.859,30.4 39.859,29.844 40.267,29.436 v1(40.267,27.98) v1@40.234,27.947 ; C608.1@50.859,30.43 C608.1@50.859,30.4 50.859,29.935 51.359,29.435 v1(51.359,27.947) ; C609.1@61.859,30.4 61.859,29.844 62.23,29.473 v1(62.23,27.947) ; C610.1@73.604,30.43 C610.1@73.604,30.4 73.604,29.844 73.076,29.317 v1(73.076,27.947) ; C611.1@84.557,30.4 84.557,29.888 83.998,29.329 v1(83.998,27.947) ; C612.1@95.519,30.4 95.519,29.811 95.021,29.313 v1(95.021,27.947) ; C613.1@106.5,30.4 106.5,29.81 106.07,29.38 v1(106.07,27.947) ; C500.2@116,41.448 116,44.97 118.339,47.309 U500.5@119.87,47.309 120.98,47.309 121.59,47.919 C502.2@122.352,47.919 ; C614.1@117.3,30.4 117.3,29.745 117.043,29.489 v1(117.043,27.947) ; C615.1@128.4,30.4 128.4,30.022 128.041,29.663 v1(128.041,27.947) ; C619.1@138.979,30.4 138.979,29.844 139.294,29.53 v1(139.294,27.947) ; C620.1@150.013,30.4 150.013,29.961 150.317,29.657 v1(150.317,27.947) ; C621.1@160.961,30.385 160.961,29.842 161.29,29.513 v1(161.29,27.947) ; C624.1@171.95,30.4 171.95,29.832 172.339,29.443 v1(172.339,27.947) ; C625.1@182.956,30.385 182.956,29.782 183.236,29.503 v1(183.236,27.947) ; C626.1@193.95,30.4 193.95,29.696 194.259,29.387 v1(194.259,27.947) ; C627.1@205.55,30.4 205.55,29.825 205.181,29.456 v1(205.181,27.947) ; C628.1@216.56,30.36 216.56,29.76 216.154,29.353 v1(216.154,27.947) ; C629.1@227.549,30.4 227.549,29.958 227.076,29.484 v1(227.076,27.947) ; C630.1@238.55,30.43 C630.1@238.55,30.4 238.55,29.825 238.1,29.374 v1(238.1,27.947) ; C631.1@249.55,30.4 249.55,29.845 249.092,29.387 v1(249.092,27.947) ; C632.1@260.55,30.4 260.55,29.607 260.124,29.181 v1(260.124,27.95) 260.121,27.947 v1(249.092,27.947) ; v1@18.263,27.947 v1(29.388,27.947) ; v1(29.388,27.947) v1@40.234,27.947 ; v1@40.234,27.947 v1(51.359,27.947) ; v1(51.359,27.947) v1(62.23,27.947) ; v1(62.23,27.947) v1(73.076,27.947) ; v1(73.076,27.947) v1(83.998,27.947) ; v1(83.998,27.947) v1(95.021,27.947) ; v1(95.021,27.947) v1(106.07,27.947) ; v1(106.07,27.947) v1(117.043,27.947) ; v1(117.043,27.947) v1(128.041,27.947) ; v1(128.041,27.947) v1(139.294,27.947) ; v1(139.294,27.947) v1(150.317,27.947) ; v1(150.317,27.947) v1(161.29,27.947) ; v1(161.29,27.947) v1(172.339,27.947) ; v1(172.339,27.947) v1(183.236,27.947) ; v1(183.236,27.947) v1(194.259,27.947) ; v1(194.259,27.947) v1(205.181,27.947) ; v1(205.181,27.947) v1(216.154,27.947) ; v1(216.154,27.947) v1(227.076,27.947) ; v1(227.076,27.947) v1(238.1,27.947) ; v1(238.1,27.947) v1(249.092,27.947)
  other v1: 7.283,1.978 3.327,11.63 5.918,11.63 8.509,11.63 11.1,11.63 256.286,11.732 258.877,11.732 261.468,11.732 264.058,11.732 245.796,11.909 248.2,11.909 250.605,11.909 253.009,11.909 13.975,12.096 16.566,12.096 19.157,12.096 21.747,12.096 235.407,12.519 237.803,12.519 240.199,12.519 242.595,12.519 24.536,12.798 27.127,12.798 29.718,12.798 32.309,12.798 156.566,12.824 159.156,12.824 161.747,12.824 164.338,12.824 102.438,12.951 105.029,12.951 107.62,12.951 110.211,12.951 224.638,13.052 227.313,13.052 229.989,13.052 232.664,13.052 147.472,13.538 35.23,13.56 37.821,13.56 40.411,13.56 43.002,13.56 167.386,13.738 170.049,13.738 172.713,13.738 175.376,13.738 178.039,13.738 180.703,13.738 183.366,13.738 186.03,13.738 213.992,14.018 216.635,14.018 219.277,14.018 221.92,14.018 206.273,14.297 208.305,14.297 211.176,14.297 189.001,14.399 191.592,14.399 194.183,14.399 89.129,14.475 91.059,14.475 75.387,14.576 77.978,14.576 80.569,14.576 83.16,14.576 45.695,14.678 48.34,14.678 50.986,14.678 53.632,14.678 56.278,14.678 58.924,14.678 61.57,14.678 205.292,14.932 207.442,15.011 212.725,15.037 96.596,15.161 99.187,15.161 101.778,15.161 104.369,15.161 89.243,16.431 75.652,16.51 77.181,16.51 80.239,16.51 168.656,16.786 171.247,16.786 173.838,16.786 176.428,16.786 157.734,16.812 160.325,16.812 162.916,16.812 165.506,16.812 117.45,16.891 112.268,16.95 211.459,17.018 214.274,17.04 133.782,17.167 136.4,17.167 139.018,17.167 154.711,17.45 216.243,17.472 151.755,17.526 92.202,17.624 95.153,17.624 98.105,17.624 101.056,17.624 104.008,17.624 106.959,17.624 62.2,17.917 58.242,17.958 149.025,18.136 123.749,18.723 141.986,18.971 216.22,19.225 57.226,19.58 142.443,19.906 89.433,20.215 92.879,20.215 96.325,20.215 99.771,20.215 103.217,20.215 106.663,20.215 110.109,20.215 117.435,20.753 214.605,20.952 132.715,21.003 134.468,21.028 84.807,21.285 82.626,21.33 57.252,21.358 212.09,21.598 152.883,21.679 158.633,21.679 164.384,21.679 170.134,21.679 175.885,21.679 181.635,21.679 112.141,21.765 133.55,22.4 136.246,22.4 131.135,22.437 62.237,22.454 209.372,22.476 151.663,22.857 141.475,22.885 145.796,22.987 125.705,23.012 115.011,23.085 118.013,23.085 202.667,23.263 204.534,23.263 206.4,23.263 71.933,23.289 75.286,23.368 185.572,23.924 188.417,23.924 120.802,24.638 124.003,24.689 202.641,24.813 199.263,25.095 2.87,37.776 5.508,37.776 8.146,37.776 10.784,37.776 13.422,37.776 16.06,37.776 18.698,37.776 21.336,37.776 246.024,37.802 249.523,37.802 253.021,37.802 256.52,37.802 260.018,37.802 263.517,37.802 103.149,38.31 105.85,38.31 108.551,38.31 25.527,38.411 29.155,38.411 32.783,38.411 235.255,38.513 237.956,38.513 240.657,38.513 36.297,38.945 39.764,38.945 43.231,38.945 93.523,39.005 96.224,39.005 98.925,39.005 225.222,39.005 227.923,39.005 230.624,39.005 156.388,39.504 159.089,39.504 161.79,39.504 86.054,39.548 151.863,39.605 82.245,39.631 88.666,39.631 91.367,39.631 214.659,39.631 217.36,39.631 220.061,39.631 46.761,39.718 50.292,39.718 53.823,39.718 180.238,39.718 182.939,39.718 185.64,39.718 147.588,39.783 115.108,39.808 118.692,39.808 122.276,39.808 192.583,40.24 206.019,40.266 208.72,40.266 211.421,40.266 73.61,40.342 76.311,40.342 79.011,40.342 57.48,40.367 59.669,40.367 61.859,40.367 168.3,40.4 171.001,40.4 173.702,40.4 82.042,40.919 188.874,40.951 207.188,41.023 210.237,41.023 213.286,41.023 194.412,41.205 119.558,41.536 90.975,41.79 134.759,42.272 137.46,42.272 140.161,42.272 155.321,42.983 160.252,42.983 165.183,42.983 170.114,42.983 175.045,42.983 179.976,42.983 142.062,43.136 75.362,43.332 89.484,43.364 216.56,43.663 93.345,44.016 97.748,44.016 102.15,44.016 190.5,44.018 58.776,44.15 61.962,44.15 84.896,44.431 151.613,44.431 155.488,44.431 159.364,44.431 163.239,44.431 167.115,44.431 170.991,44.431 174.866,44.431 178.742,44.431 182.618,44.431 124.003,44.894 117.555,45.142 216.513,45.259 57.925,45.701 142.113,45.79 86.309,46.431 89.637,46.463 94.374,46.463 99.111,46.463 105.867,46.463 116.18,46.946 214.655,46.967 129.904,47.127 132.605,47.127 135.306,47.127 151.663,47.606 155.796,47.606 159.929,47.606 164.062,47.606 168.195,47.606 172.327,47.606 176.46,47.606 180.593,47.606 184.726,47.606 190.221,47.682 209.372,48.315 57.925,48.47 60.102,48.47 62.279,48.47 85.903,49.024 119.278,49.079 83.058,49.352 77.394,49.403 203.352,49.46 206.908,49.46 62.865,50.019 71.45,50.222 74.778,50.222 93.802,51.137 96.951,51.137 100.099,51.137 103.247,51.137 106.396,51.137 109.544,51.137 112.693,51.137 115.841,51.137 64.287,51.543
  other v2: 64.5,15.95 65.5,15.95 66.5,15.95 67.5,15.95 68.5,15.95 69.5,15.95 70.5,15.95 196.75,15.95 197.75,15.95 198.75,15.95 199.75,15.95 200.75,15.95 201.75,15.95 202.75,15.95 64.5,16.95 65.5,16.95 66.5,16.95 67.5,16.95 68.5,16.95 69.5,16.95 70.5,16.95 196.75,16.95 197.75,16.95 198.75,16.95 199.75,16.95 200.75,16.95 201.75,16.95 202.75,16.95 117.043,17.869 64.5,17.95 65.5,17.95 66.5,17.95 67.5,17.95 68.5,17.95 69.5,17.95 70.5,17.95 196.75,17.95 197.75,17.95 198.75,17.95 199.75,17.95 200.75,17.95 201.75,17.95 202.75,17.95 116.493,18.819 117.593,18.819 117.043,19.769 64.5,41.95 65.5,41.95 66.5,41.95 67.5,41.95 68.5,41.95 69.5,41.95 70.5,41.95 196.75,41.95 197.75,41.95 198.75,41.95 199.75,41.95 200.75,41.95 201.75,41.95 202.75,41.95 64.5,42.95 65.5,42.95 66.5,42.95 67.5,42.95 68.5,42.95 69.5,42.95 70.5,42.95 196.75,42.95 197.75,42.95 198.75,42.95 199.75,42.95 200.75,42.95 201.75,42.95 202.75,42.95 64.5,43.95 65.5,43.95 66.5,43.95 67.5,43.95 68.5,43.95 69.5,43.95 70.5,43.95 196.75,43.95 197.75,43.95 198.75,43.95 199.75,43.95 200.75,43.95 201.75,43.95 202.75,43.95
LIN: C501.1 C502.1 J400.2 U500.6 | length 10.9
  Bottom Layer w0.254: C502.1@122.326,46.369 C502.1@122.352,46.395
  Bottom Layer w0.5: U500.6@119.87,46.039 121.996,46.039 122.326,46.369 128.352,46.369 J400.2@129.94,44.782
NetC100_2: C100.2 C109.1 | length 3.1
  Bottom Layer w1.2: C100.2@143.408,16.048 144.678,17.318 C109.1@144.678,18.575
NetC103_1: C103.1 J100.5 R101.1 | length 10.9
  Bottom Layer w0.45: J100.5@137.56,18.7 139.67,20.81 C103.1@146.228,20.81 R101.1@147.588,20.81
NetC108_1: C108.1 J100.4 R100.1 | length 11
  Bottom Layer w0.45: J100.4@135.02,18.7 137.953,21.633 C108.1@143.434,21.633 R100.1@144.805,21.633
NetC205_1: C205.1 R204.1 R207.2 | length 2.6
  Bottom Layer w0.4: R204.1@121.031,17.407 C205.1@121.031,18.727 R207.2@121.031,20.023
NetC316_2: C316.2 R306.2 U300.12 | length 4
  Bottom Layer w0.254: C316.2@75.024,19.916 C316.2@75.058,19.95
  Bottom Layer w0.45: U300.12@71.075,19.9 R306.2@72.984,19.9 ; R306.2@73,19.916 C316.2@75.024,19.916
NetC333_2: C333.2 R316.2 U301.12 | length 3.5
  Bottom Layer w0.254: R316.2@205.181,19.9 R316.2@205.185,19.896
  Bottom Layer w0.4: U301.12@203.325,19.9 R316.2@205.181,19.9 ; R316.2@205.185,19.896 C333.2@206.836,19.896
NetC400_2: C400.2 C405.1 | length 3.2
  Bottom Layer w1: C400.2@143.408,42.058 143.873,42.058 144.628,42.813 C405.1@144.628,44.49
NetC403_1: C403.1 J400.5 R401.1 | length 10.8
  Bottom Layer w0.45: J400.5@137.56,44.782 139.63,46.852 C403.1@146.177,46.852 R401.1@147.523,46.852
NetC404_1: C404.1 J400.4 R400.1 | length 10.8
  Bottom Layer w0.45: J400.4@135.02,44.782 137.878,47.639 C404.1@143.341,47.639 R400.1@144.678,47.639
NetC616_2: C616.2 R606.2 U600.12 | length 3.6
  Bottom Layer w0.254: R606.2@72.952,45.9 R606.2@72.974,45.922 ; C616.2@74.696,45.922 C616.2@74.701,45.928
  Bottom Layer w0.45: U600.12@71.075,45.9 R606.2@72.952,45.9 ; R606.2@72.974,45.922 C616.2@74.696,45.922
NetC633_2: C633.2 R616.2 U601.12 | length 3.6
  Bottom Layer w0.254: C633.2@206.951,45.9 C633.2@206.963,45.912
  Bottom Layer w0.45: U601.12@203.325,45.9 C633.2@206.951,45.9
NetD300_1: D300.1 D300.3 D300.4 D300.6 D301.2
  other v1: 57.48,2.908 58.809,2.908 60.139,2.908 61.468,2.908 57.48,4.281 58.809,4.281 60.139,4.281 57.48,5.577 58.809,5.577 60.139,5.577 61.468,5.577 57.48,9.869 58.809,9.869 60.139,9.869 61.468,9.869
NetD302_2: D302.2 D303.1 D303.3 D303.4 D303.6
  other v1: 128.829,2.91 130.158,2.91 131.487,2.91 132.817,2.91 130.158,4.281 131.487,4.281 132.817,4.281 128.829,5.577 130.158,5.577 131.487,5.577 132.817,5.577 128.829,10.098 130.158,10.098 131.487,10.098 132.817,10.098
NetD304_1: D304.1 D304.3 D304.4 D304.6 D305.2
  other v1: 46.482,2.908 47.811,2.908 49.141,2.908 50.47,2.908 46.482,4.281 47.811,4.281 49.141,4.281 46.482,5.577 47.811,5.577 49.141,5.577 50.47,5.577 46.482,10.073 47.811,10.073 49.141,10.073 50.47,10.073
NetD306_2: D306.2 D307.1 D307.3 D307.4 D307.6
  other v1: 117.907,2.908 119.236,2.908 120.565,2.908 121.895,2.908 119.236,4.281 120.565,4.281 121.895,4.281 117.907,5.577 119.236,5.577 120.565,5.577 121.895,5.577 117.907,10.098 119.236,10.098 120.565,10.098 121.895,10.098
NetD308_1: D308.1 D308.3 D308.4 D308.6 D309.2
  other v1: 35.433,2.908 36.762,2.908 38.092,2.908 39.421,2.908 35.433,4.281 36.762,4.281 38.092,4.281 35.433,5.577 36.762,5.577 38.092,5.577 39.421,5.577 35.433,10.098 36.762,10.098 38.092,10.098 39.421,10.098
NetD310_2: D310.2 D311.1 D311.3 D311.4 D311.6
  other v1: 106.909,2.91 108.238,2.91 109.567,2.91 110.896,2.91 108.238,4.281 109.567,4.281 110.896,4.281 106.909,5.577 108.238,5.577 109.567,5.577 110.896,5.577 106.909,10.098 108.238,10.098 109.567,10.098 110.896,10.098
